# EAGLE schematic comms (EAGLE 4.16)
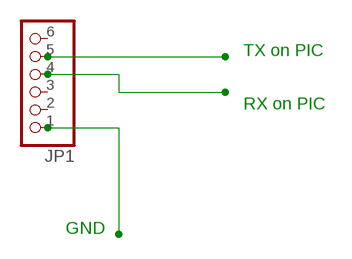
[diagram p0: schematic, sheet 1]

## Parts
JP1  PINHD-1X6  [1X06]

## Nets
N$1: JP1.1
N$2: JP1.4
N$3: JP1.5
Unconnected: JP1.2 JP1.3 JP1.6

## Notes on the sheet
- TX on PIC
- RX on PIC
- GND

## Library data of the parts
JP1 = pinhead:PINHD-1X6: PIN HEADER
